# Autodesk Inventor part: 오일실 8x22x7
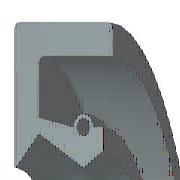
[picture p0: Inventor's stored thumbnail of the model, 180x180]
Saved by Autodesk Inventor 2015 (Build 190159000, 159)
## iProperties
IsCustomPart: 1
Company: 한국ATC센터
Created: 2014-07
Part Number: 오일실 8x22x7
Material: 고무
Description: 오일-실
Document SubType Name: Modeling
Standard: KS B 2804
Designer: KYOUNG IL JANG
Standards Organization: KS
Language: ko-KR
Size Designation: D - 8 22 7
Categories: <MemberInstance><Categories><Category DisplayName="샤프트 부품" InternalName="7f7aeb1f-a693-4053-b835-cee3144e0d98" Mnemonic="SHFT"><Category DisplayName="실링" Intern
Density: 0.93 g/cm^3
Appearance: 고무 - 검은색 - 버전 1.1
Author: KYOUNG IL JANG
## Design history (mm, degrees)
revolve "본체" stored, may be unused: angle "d17" = 90 deg
revolve "스프링1" stored, may be unused: angle "d18" = 90 deg
body "Solid1"
sketch "스케치1"
  geometry: L1 (0, 11)-(7, 11); L2 (7, 9.25)-(1.75, 9.25); L3 (1.75, 5.75)-(4.9, 4); L4 (4.9, 4)-(0, 4); L5 (0, 0)-(9.586, 0) reference; L6 (4.9, 4)-(6.3, 4.875); L7 (0, 18)-(0, -3) reference; L8 (-1.941, 0)-(11.507, 0) reference; L9 (4.2, 6.1)-(1.75, 6.59); L10 (1.75, 6.59)-(1.75, 9.25); L11 (0, 11)-(0, 4.088); L12 (4.9, 4)-(0, 4); L13 (1.75, 5.75)-(0.152, 4.028); L14 (7, 11)-(7, 9.25); L15 (5.6, 6.1)-(6.3, 6.1); L16 (6.3, 6.1)-(6.3, 4.875); C1 r 0.455 at (4.9, 6.1); A1 r 0.7 centre (4.9, 6.1) between (5.6, 6.1) and (4.2, 6.1); A2 r 0.088 centre (0.088, 4.088) between (0, 4.088) and (0.152, 4.028); 1 further point
  constraints: 28 end point, 5 horizontal alignment, 5 point on line, 4 point on circle, 4 vertical alignment, 3 centre point, 3 tangent, 2 collinear, 2 horizontal, 2 perpendicular, 1 coincident, 1 parallel
  dimensions: "d0" = 22 diameter of L1 L5 (= SD2); "d1" = 1.75 distance of L1.end L2.start (= SD); "d2" = 0.91 diameter of C1 (= SPDI); "d3" = 1.4 diameter of A1 (= SPDA); "d4" = 8 diameter of L3.end L5 (= NND); "d5" = 11.5 diameter of L3.start L5 (= TKDM); "d7" = 13.18 diameter of L9.end L5 (= TKDM + 0.24 x SWDT); "d8" = 1.75 distance between parallel lines of L11 L10 (= SD); "d9" = 4.9 distance from line of L11 C1.centre (= SPDST); "d10" = 12.2 diameter of C1.centre L5 (= HLDM); "d11" = 0.0875 radius of A2 (= 0.25 x LAB); "d12" = 6.3 distance between parallel lines of L11 L16 (= SDI); "d13" = 9.75 diameter of L6.end L5 (= ABDM); "d14" = 7 distance from line of L11 L1.end (= SWDT)
fillet "모깎기1" dims "d6" = 0.3 (= RR)
other parameters: "SD2" = 22 [user parameter; used in 1 equation term], "SWDT" = 7 [user parameter; used in 2 equation terms], "RR" = 0.3 [user parameter; used in 1 equation term], "SD" = 1.75 [user parameter; used in 2 equation terms], "NND" = 8 [user parameter; used in 1 equation term], "SPDA" = 1.4 [user parameter; used in 1 equation term], "SPDI" = 0.91 [user parameter; used in 1 equation term], "TKDM" = 11.5 [user parameter; used in 2 equation terms], "HLDM" = 12.2 [user parameter; used in 1 equation term], "ABDM" = 9.75 [user parameter; used in 1 equation term], "SDI" = 6.3 [user parameter; used in 1 equation term], "SPDST" = 4.9 [user parameter; used in 1 equation term], "LAB" = 0.35 [user parameter; used in 1 equation term], "d15" = 0, "d16" = 0, "d19" = 0
